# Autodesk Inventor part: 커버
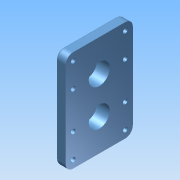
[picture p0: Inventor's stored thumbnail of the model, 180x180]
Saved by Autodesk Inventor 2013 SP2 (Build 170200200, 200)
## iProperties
Created: 2026-10
Part Number: 커버
Material: Generic
Document SubType Name: Modeling
Designer: a
Density: 1 g/cm^3
Author: a
변환 표준: STEP AP214IS
전처리기: Build: 200, Release: 2013 SP2 Update 6 - Date: Thu 07/17/2014
전송 단위: 밀리미터
불확실성: 0.01
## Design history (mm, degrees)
node "커버1"
node "솔리드1"
node "기준1"
